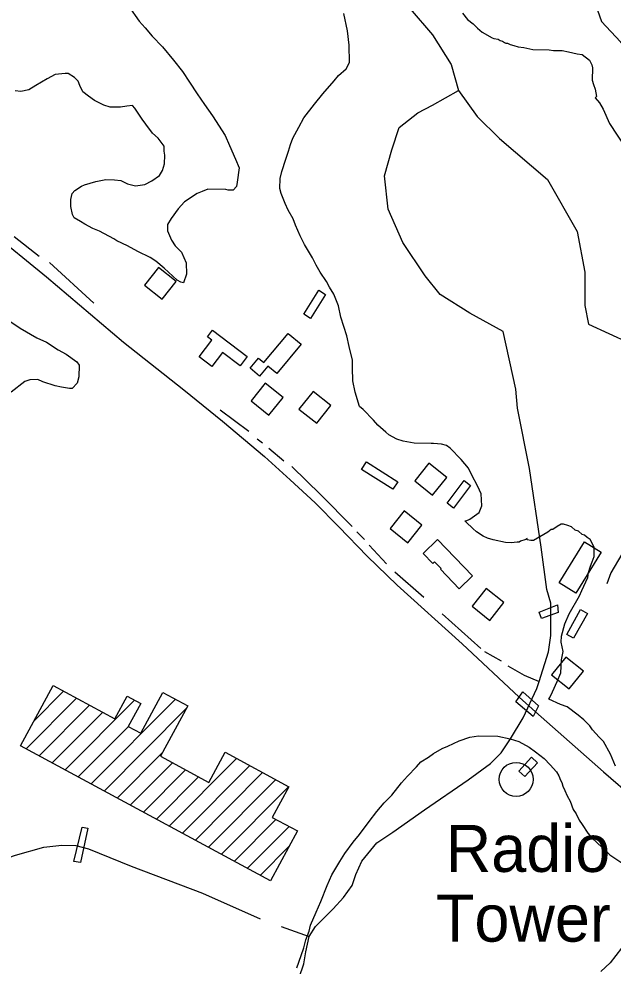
# Model space of a CAD drawing. Extents: x 3355677 to 3393573, y 612928 to 638357.
# Drawn here: x 3383445 to 3384493, y 626510 to 628181 of the extents above; entities that cross this region are included whole.
import ezdxf

# ---------------------------------------------------------------- set-up
doc = ezdxf.new("R2010")
doc.units = 0
for name, color, linetype in [('V-BLDG-OTLN', 7, 'Continuous'), ('V-BRDG-OTLN', 7, 'Continuous'), ('V-ROAD-CNTR', 7, 'Continuous'), ('V-SITE-VEGE', 7, 'Continuous'), ('V-TOPO-SHOR', 7, 'Continuous'), ('V-TOPO-TOWR', 7, 'Continuous'), ('V-TOPO-TOWR-IDEN', 7, 'Continuous')]:
    doc.layers.add(name, color=color, linetype=linetype)

msp = doc.modelspace()

# ---------------------------------------------------------------- linework, layer by layer
at = {"layer": 'V-BLDG-OTLN'}
for p, q in [((3383471.6, 626942.6), (3383523.8, 626995.1)), ((3383458, 626893.5), (3383546.7, 626982.7)), ((3383481, 626881.2), (3383569.6, 626970.3)), ((3383526.8, 626856.4), (3383649.1, 626979.2)), ((3383572.7, 626831.6), (3383721.4, 626981)), ((3383503.9, 626868.8), (3383592.6, 626957.9)), ((3383595.7, 626819.2), (3383740.2, 626964.5)), ((3383549.8, 626844), (3383638.1, 626932.7)), ((3383618.6, 626806.8), (3383698.3, 626886.9)), ((3383710.3, 626757.3), (3383829, 626876.6)), ((3383641.5, 626794.4), (3383715.8, 626869.1)), ((3383664.5, 626782), (3383738.7, 626856.7)), ((3383733.3, 626744.9), (3383852, 626864.2)), ((3383687.4, 626769.6), (3383761.7, 626844.3)), ((3383756.2, 626732.5), (3383874.9, 626851.8)), ((3383779.2, 626720.1), (3383897.9, 626839.4)), ((3383802.1, 626707.7), (3383920.8, 626827)), ((3383825, 626695.3), (3383898.4, 626769.1)), ((3383848, 626682.9), (3383921.4, 626756.7)), ((3383870.9, 626670.5), (3383921.3, 626721.2))]:
    msp.add_line(p, q, dxfattribs=at)
for points in [[(3383666.4, 627711.6), (3383697.6, 627686.6), (3383722.6, 627717.9), (3383691.3, 627742.8)], [(3383947.3, 627660.3), (3383973.9, 627702.7), (3383985.8, 627695.2), (3383959.2, 627652.9)], [(3383786.5, 627632.1), (3383847.6, 627585.7), (3383835.1, 627569.2), (3383804.2, 627592.6), (3383785.3, 627567.8), (3383762.7, 627584.9), (3383785.4, 627614.8), (3383777.8, 627620.6)], [(3383942.6, 627607.7), (3383899.9, 627556), (3383884.3, 627568.9), (3383869.6, 627551.1), (3383852.9, 627564.9), (3383867.7, 627582.8), (3383877.2, 627575), (3383919.7, 627626.5)], [(3383854.6, 627507.3), (3383885.8, 627482.3), (3383910.8, 627513.6), (3383879.5, 627538.5)], [(3383938.9, 627492.9), (3383970.2, 627468), (3383995.1, 627499.3), (3383963.9, 627524.2)], [(3384057.8, 627399.7), (3384113.1, 627364.8), (3384104.7, 627351.4), (3384049.3, 627386.3)], [(3384143.2, 627366.2), (3384174.5, 627341.2), (3384199.5, 627372.5), (3384168.2, 627397.4)], [(3384200.5, 627326.7), (3384230.5, 627366.7), (3384241.7, 627358.3), (3384211.7, 627318.3)], [(3384099.5, 627282.1), (3384130.8, 627257.1), (3384155.8, 627288.4), (3384124.5, 627313.3)], [(3384183.5, 627262.6), (3384244.8, 627198.8), (3384221.2, 627176.1), (3384188.4, 627210.3), (3384189.6, 627211.4), (3384177.9, 627223.6), (3384175, 627220.7), (3384158.2, 627238.2)], [(3384471.9, 627240.3), (3384426.9, 627168.1), (3384397.6, 627186.3), (3384442.5, 627258.6)], [(3384244.1, 627145.2), (3384275.4, 627120.2), (3384300.3, 627151.5), (3384269, 627176.4)], [(3384411.1, 627095.4), (3384435.3, 627139.1), (3384447.6, 627132.4), (3384423.3, 627088.6)], [(3384384.4, 627024.2), (3384415.7, 626999.3), (3384440.6, 627030.5), (3384409.3, 627055.5)], [(3383888.7, 626660.9), (3383448, 626899), (3383505.3, 627005), (3383614.1, 626946.3), (3383635.8, 626986.4), (3383660, 626973.4), (3383638, 626932.7), (3383660, 626920.9), (3383699, 626993.1), (3383742.8, 626969.4), (3383694.8, 626880.4), (3383780.2, 626834.3), (3383808.9, 626887.5), (3383921.2, 626826.8), (3383891.9, 626772.6), (3383936.2, 626748.7)], [(3384326.4, 626854.2), (3384349, 626878.8), (3384359.6, 626869.1), (3384337, 626844.5)]]:
    msp.add_lwpolyline(points, close=True, dxfattribs=at)
at = {"layer": 'V-BRDG-OTLN'}
msp.add_line((3384355.9, 626959), (3384327.2, 626984.8), dxfattribs=at)
for points in [[(3384362.3, 627134.7), (3384395, 627147.3), (3384395.8, 627134.3), (3384366.8, 627123.5)], [(3384333.7, 626993.9), (3384361.3, 626969.3), (3384351.7, 626950.8), (3384321.3, 626976.4)], [(3383556.6, 626755.3), (3383566.8, 626753.3), (3383553.9, 626693), (3383541.8, 626695)]]:
    msp.add_lwpolyline(points, close=True, dxfattribs=at)
at = {"layer": 'V-ROAD-CNTR'}
msp.add_line((3384327.2, 626984.8), (3384355.9, 626959), dxfattribs=at)
for points in [[(3384458.6, 628217.1), (3384472.2, 628176.9), (3384505.9, 628140.7), (3384569.9, 628084.9), (3384675.9, 627991.5), (3384767.7, 627901.9), (3384860.5, 627828.6), (3384920.3, 627777.8), (3384955.1, 627738.4), (3384982.4, 627705.8), (3385013.5, 627658.8), (3385039.4, 627589.3), (3385080, 627502.1), (3385116, 627419.2), (3385139.1, 627366.5), (3385165, 627324.2), (3385200.3, 627282.4), (3385243.4, 627243.8), (3385306.6, 627186.1), (3385384, 627120.1), (3385430.1, 627074.2)], [(3383155.6, 628004.1), (3383257, 627923.4), (3383393.5, 627807.3), (3383494, 627726), (3383629.5, 627611), (3383735.7, 627526.8), (3383804, 627471.4), (3383878, 627409.1), (3383923.2, 627368.4), (3383967.4, 627327.7), (3384009, 627285.2), (3384059.1, 627233.3), (3384112.1, 627182), (3384226.9, 627078.6), (3384327.2, 626984.8)], [(3384355.9, 626959), (3384476, 626852.9), (3384587.4, 626756.8), (3384720.6, 626634.3), (3384831.3, 626537.5), (3384901.3, 626477.8)]]:
    msp.add_lwpolyline(points, dxfattribs=at)
at = {"layer": 'V-SITE-VEGE'}
for points in [[(3383639, 628203), (3383657.2, 628177.5), (3383668, 628165.3), (3383679.9, 628150.9), (3383698.3, 628132), (3383717.7, 628108.7), (3383733.8, 628088.7), (3383745.6, 628069.9), (3383759.6, 628048.9), (3383772.5, 628030), (3383786.4, 628010.1), (3383809, 627975.8), (3383816.4, 627958.2), (3383827, 627933.9), (3383833.4, 627918.5), (3383829.7, 627893.3), (3383828.5, 627885.6), (3383823, 627879.1), (3383814.2, 627879.3), (3383809.8, 627880.4), (3383778, 627880.9), (3383768.1, 627876.6), (3383759.3, 627873.5), (3383737.1, 627858.4), (3383726, 627846.5), (3383713.7, 627829.1), (3383707, 627818.3), (3383706.8, 627807.3), (3383714.3, 627790.8), (3383720.7, 627780.8), (3383731.5, 627769.7), (3383740, 627750.9), (3383740.8, 627731.2), (3383735.1, 627715.9), (3383730.8, 627717.1), (3383724.2, 627720.5), (3383701.5, 627741.6), (3383686.3, 627753.9), (3383676.6, 627760.6), (3383654.8, 627770.8), (3383636.3, 627780.9), (3383617.8, 627789.9), (3383612.3, 627793.3), (3383587.3, 627806.8), (3383575.3, 627811.4), (3383561.2, 627819.2), (3383553.6, 627823.7), (3383542.7, 627830.5), (3383539.5, 627836), (3383536.4, 627850.3), (3383536.6, 627862.4), (3383538.9, 627873.3), (3383543.4, 627878.7), (3383555.5, 627886.2)], [(3384199.2, 627428.7), (3384190.5, 627431), (3384176.2, 627432.3), (3384171.9, 627432.3), (3384142.3, 627432.8), (3384122.6, 627436.3), (3384111.7, 627439.8), (3384097.5, 627447.6), (3384092.1, 627452.1), (3384078, 627464.4), (3384070.5, 627473.2), (3384052.1, 627492.1), (3384045.6, 627497.7), (3384038.3, 627523), (3384034.2, 627542.8), (3384033.4, 627565.9), (3384033.6, 627579), (3384027.4, 627603.2), (3384023.2, 627621.9), (3384012.7, 627655), (3384008.6, 627674.8), (3384000.2, 627695.7), (3383992.7, 627707.9), (3383987.3, 627717.8), (3383976.6, 627734.4), (3383969.1, 627746.6), (3383962.7, 627759.8), (3383948.8, 627783.1), (3383941.3, 627798.5), (3383932.8, 627817.3), (3383928.6, 627828.3), (3383920, 627843.8), (3383914.7, 627855.9), (3383907.3, 627873.5), (3383905.2, 627882.3), (3383905.5, 627899.9), (3383908.9, 627911.9), (3383915.8, 627933.7), (3383920.4, 627947.9), (3383923.9, 627959.9), (3383928.4, 627970.8), (3383938.6, 627990.4), (3383947.6, 628006.7), (3383966.5, 628030.6), (3383981, 628049), (3384001.1, 628071.8), (3384008.9, 628081.5), (3384022.2, 628093.4), (3384027.9, 628104.3), (3384027.2, 628135), (3384024.3, 628160.2), (3384018.1, 628191)], [(3384227.6, 628191.4), (3384236.2, 628180.3), (3384245.9, 628172.5), (3384253.5, 628164.7), (3384262.2, 628158), (3384279.6, 628147.9), (3384282.8, 628146.7), (3384290.5, 628145.5), (3384293.8, 628143.3), (3384298.1, 628142.1), (3384301.4, 628139.9), (3384303.6, 628138.7), (3384306.8, 628138.7), (3384311.2, 628136.4), (3384317.7, 628134.2), (3384325.4, 628131.9), (3384335.2, 628130.6), (3384351.6, 628127.1), (3384380.1, 628126.7), (3384387.8, 628125.5), (3384403.1, 628125.3), (3384414.1, 628122.9), (3384429.4, 628119.4), (3384438.1, 628118.2), (3384451.1, 628108.2), (3384455.4, 628100.4), (3384456.4, 628094.9), (3384456.1, 628073), (3384458.2, 628065.3)], [(3383555.5, 627886.2), (3383561, 627888.3), (3383580.9, 627894.6), (3383598.5, 627897.7), (3383613.8, 627897.4), (3383624.7, 627896.2), (3383636.7, 627890.5), (3383650.9, 627887), (3383667.4, 627889), (3383679.6, 627895.4), (3383692.9, 627905.1), (3383698.5, 627913.8), (3383701.9, 627925.8), (3383702.1, 627941.1), (3383701.1, 627947.7), (3383701.3, 627956.5), (3383690.5, 627970.9), (3383680.8, 627979.8), (3383668.9, 627995.3), (3383662.5, 628004.2), (3383649.6, 628024.1), (3383645.3, 628028.6), (3383635.4, 628027.6), (3383624.4, 628025.6), (3383605.8, 628025.8), (3383594.8, 628029.3), (3383578.5, 628037.2), (3383567.6, 628045), (3383557.9, 628052.8), (3383552.6, 628063.9), (3383549.4, 628071.6), (3383542.9, 628078.2), (3383532, 628085), (3383526.6, 628085.1), (3383509, 628083.1), (3383494.6, 628075.6), (3383474.7, 628063.9), (3383462.6, 628056.4), (3383448.3, 628053.3), (3383438.4, 628054.5)], [(3384458.2, 628065.3), (3384461.4, 628057.6), (3384463.4, 628044.4), (3384461.2, 628042.2), (3384468.7, 628033.4), (3384475.1, 628022.3), (3384486.8, 627996.9), (3384514.7, 627953.8)], [(3383425.3, 627650.3), (3383447, 627635.7), (3383476.4, 627618.8), (3383493.8, 627610.9), (3383514.4, 627597.5), (3383528.6, 627589.6), (3383547, 627576.2), (3383551.3, 627570.6), (3383551, 627549.8), (3383547.6, 627538.9), (3383538.7, 627529.1), (3383534.3, 627529.2), (3383520.1, 627531.6), (3383509.2, 627534), (3383487.3, 627540.8), (3383478.6, 627545.3), (3383464.4, 627544.5), (3383455.5, 627541.3), (3383431.2, 627523)], [(3384497.1, 626863.1), (3384488.6, 626884.1), (3384475.8, 626906.2), (3384468.2, 626913.9), (3384456.4, 626927.3), (3384452.1, 626933.9), (3384441.3, 626945), (3384431.5, 626952.8), (3384412, 626967.4), (3384400, 626971.9), (3384379.3, 626981), (3384381.5, 626984.2), (3384386, 626994), (3384394, 627012.6), (3384400.8, 627027.8), (3384402.2, 627050.8), (3384404.6, 627065.1), (3384401.5, 627081.5), (3384401.7, 627092.5), (3384407.5, 627114.3), (3384415.4, 627131.8), (3384433.4, 627163.3), (3384437.9, 627173.1), (3384448.1, 627196), (3384449.3, 627204.8), (3384452.8, 627215.7), (3384456.2, 627223.3), (3384459.6, 627233.1), (3384459.8, 627248.5), (3384456.6, 627255.1), (3384452.3, 627262.8), (3384446.9, 627266.2), (3384442.6, 627270.6), (3384438.2, 627271.8), (3384431.7, 627277.4), (3384426.3, 627279.6), (3384419.8, 627285.2), (3384413.2, 627287.5), (3384405.6, 627289.8), (3384401.2, 627289.9), (3384394.5, 627285.6), (3384386.8, 627280.2), (3384383.5, 627280.2), (3384378, 627275.9), (3384352.5, 627260.9), (3384348.1, 627261), (3384341.6, 627262.2), (3384341.6, 627264.4), (3384337.2, 627262.3), (3384329.5, 627260.2), (3384327.3, 627258), (3384324, 627258.1), (3384313, 627257.1), (3384303.1, 627257.3), (3384281.3, 627262), (3384271.5, 627265.4), (3384263.8, 627268.8), (3384251.9, 627276.6), (3384245.4, 627282.2), (3384233.5, 627293.3), (3384231.3, 627295.6), (3384233.5, 627295.5), (3384240.1, 627298.7), (3384256.8, 627310.5), (3384261.3, 627322.5), (3384260.5, 627343.4), (3384254.1, 627356.6), (3384243.4, 627377.6), (3384238.1, 627388.6), (3384225.2, 627404.2), (3384205.7, 627424.2), (3384199.2, 627428.7)], [(3383935.1, 626507.4), (3383943.1, 626529.2), (3383947.6, 626542.3), (3383951.1, 626556.5), (3383956.8, 626571.8), (3383959.2, 626582.7), (3383969.3, 626605.6), (3383977.3, 626624.1), (3383988.7, 626652.5), (3383996.6, 626671), (3384011.2, 626694.9), (3384020.1, 626709), (3384034.7, 626728.6), (3384045.8, 626742.7), (3384062.6, 626765.4), (3384076, 626782.8), (3384089.4, 626798), (3384102.7, 626812), (3384119.5, 626833.7), (3384130.6, 626845.6), (3384146.2, 626861.8), (3384154, 626870.5), (3384167.3, 626879.1), (3384176.1, 626885.5), (3384191.6, 626894.1), (3384201.5, 626898.3), (3384221.4, 626907.9), (3384240.1, 626914.2), (3384255.5, 626916.2), (3384289.5, 626915.7), (3384311.4, 626911), (3384326.6, 626906.4), (3384345.1, 626896.3), (3384356, 626888.5), (3384371.2, 626876.2), (3384382, 626865.1), (3384392.8, 626852.9), (3384397.1, 626846.2), (3384400.2, 626838.5), (3384402.4, 626834.1), (3384404.5, 626827.5), (3384407.6, 626819.8), (3384411.9, 626810.9), (3384417.2, 626801), (3384422.5, 626786.7), (3384427.9, 626778.9), (3384433.2, 626767.9), (3384438.6, 626760.1), (3384448.2, 626744.6), (3384455.8, 626735.8), (3384473.1, 626720.2), (3384487.2, 626706.8), (3384510, 626691.1)], [(3384553.9, 626614.9), (3384544.8, 626596.3), (3384520.2, 626560.5), (3384507.9, 626542.1), (3384487.8, 626516), (3384471.1, 626500.9)]]:
    msp.add_lwpolyline(points, dxfattribs=at)
at = {"layer": 'V-TOPO-SHOR'}
for p, q in [((3383480.6, 627761.9), (3383436.5, 627796.9)), ((3383577.2, 627679.6), (3383499.1, 627751.4)), ((3383800.2, 627491.9), (3383850.8, 627454)), ((3383865.5, 627440.7), (3383874.7, 627433.1)), ((3383885.7, 627423.7), (3383912.4, 627401.9)), ((3384040.9, 627276.3), (3384054.7, 627263.1)), ((3384062.9, 627252.7), (3384093.2, 627219.7)), ((3384107.8, 627205.6), (3384159.3, 627161.1)), ((3384191.5, 627131.9), (3384259.5, 627070.5)), ((3384266.4, 627065.3), (3384295.5, 627048.6)), ((3383907.5, 626580.3), (3383956.8, 626562.6))]:
    msp.add_line(p, q, dxfattribs=at)
for points in [[(3384135.3, 628199), (3384174.6, 628153.2), (3384207.3, 628100.8), (3384220.4, 628055), (3384253.1, 628009.2), (3384292.4, 627970), (3384377.4, 627898), (3384429.8, 627806.4), (3384442.9, 627734.4), (3384442.9, 627675.5), (3384449.4, 627642.8), (3384521.4, 627610), (3384567.2, 627590.4), (3384593.4, 627551.1), (3384593.4, 627479.2), (3384580.3, 627420.3), (3384567.2, 627367.9), (3384554.1, 627335.2), (3384528, 627282.8), (3384508.3, 627237), (3384488.7, 627204.3), (3384482.1, 627184.7)], [(3384321.3, 627528), (3384298.9, 627629.7), (3384240, 627662.4), (3384187.7, 627695.1), (3384161.5, 627727.8), (3384122.2, 627786.7), (3384096.1, 627845.6), (3384089.5, 627904.5), (3384102.6, 627950.3), (3384115.7, 627989.6), (3384148.4, 628015.8), (3384174.6, 628028.9), (3384220.4, 628055)], [(3383939.1, 626490.2), (3383947.8, 626514.3), (3383950.9, 626535.7), (3383956.8, 626562.6), (3383968.2, 626580.1), (3383999.4, 626611.3), (3384017.4, 626631.5), (3384032.6, 626652.7), (3384039.3, 626672.1), (3384049.9, 626695.3), (3384076.4, 626727.5), (3384104.6, 626746.6), (3384160.1, 626785.8), (3384237.1, 626838.7), (3384276.6, 626867.9), (3384295.5, 626886.3), (3384311.7, 626911.2), (3384334.5, 626948.1), (3384358.5, 626999.9), (3384362.5, 627012.4), (3384379, 627064.7), (3384383.1, 627093.5), (3384383, 627150.3), (3384375.9, 627174.6), (3384365.8, 627249.1), (3384345.4, 627388.1), (3384324.6, 627494.5), (3384321.3, 627528)], [(3383926.2, 627391.5), (3383977.6, 627341.4), (3384032.7, 627285.7)], [(3384307.4, 627040), (3384336.1, 627023.8), (3384362.5, 627012.4)], [(3383114.3, 626424), (3383139, 626465.5), (3383201.4, 626532.6), (3383282.6, 626612.4), (3383331.7, 626664.7), (3383337.5, 626667.7), (3383356.1, 626677.4), (3383439.3, 626706), (3383488.8, 626720.2), (3383520.5, 626723.5), (3383545.6, 626723.1), (3383567.9, 626717.2), (3383642.8, 626686.4), (3383768.7, 626639), (3383870.4, 626593.8)]]:
    msp.add_lwpolyline(points, dxfattribs=at)
at = {"layer": 'V-TOPO-TOWR'}
msp.add_line((3384321.9, 626839.7), (3384321.9, 626839.7), dxfattribs=at)
msp.add_circle((3384321.9, 626839.7), 30, dxfattribs=at)

# ---------------------------------------------------------------- texts
at = {"layer": 'V-TOPO-TOWR-IDEN'}
for s, p in [('Radio', (3384197.8, 626676.4)), ('Tower', (3384180.6, 626553.4))]:
    msp.add_text(s, height=83, dxfattribs=at).set_placement(p)

doc.saveas('drawing.dxf')
